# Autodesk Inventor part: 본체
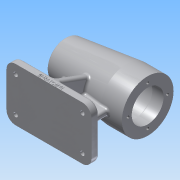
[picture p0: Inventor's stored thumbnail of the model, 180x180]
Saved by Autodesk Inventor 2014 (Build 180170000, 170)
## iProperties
Created: 2018-09
Part Number: 본체
Material: 알루미늄 6061
Document SubType Name: Modeling
Designer: 701-16
Density: 2.71 g/cm^3
Appearance: 알루미늄 - 평지
Mass: 735.408 g
Surface Area: 665.229 cm^2
Volume: 271.368 cm^3
Author: 701-16
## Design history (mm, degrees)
sketch "스케치1"
  geometry: L1 (44, 35)-(-44, 35); L2 (-56, 23)-(-56, -23); L3 (-44, -35)-(44, -35); L4 (56, -23)-(56, 23); L5 (56, 35)-(-56, -35); L6 (-56, 35)-(56, -35); A1 r 12 centre (44, -23) between (44, -35) and (56, -23); A2 r 12 centre (44, 23) between (56, 23) and (44, 35); A3 r 12 centre (-44, 23) between (-44, 35) and (-56, 23); A4 r 12 centre (-44, -23) between (-56, -23) and (-44, -35); 1 further point
  constraints: 12 end point, 8 point on circle, 8 point on line, 8 tangent, 4 centre point, 2 equal radius, 2 midpoint, 2 parallel, 1 horizontal, 1 perpendicular
  dimensions: "d0" = 112 distance of L6.end L5.end; "d1" = 70 distance of L5.end L6.start; "d2" = 12 radius of A1; "d3" = 12 radius of A2
extrude "돌출1" new body sketch "스케치1" distance "d4" = 10; taper "d5" = 0 deg
node "작업 평면1"
sketch "스케치2"
  geometry: L1 (0, 35)-(10, 35) reference; L2 (10, 35)-(10, -35) reference; L3 (10, -35)-(0, -35) reference; L4 (0, -35)-(0, 35) reference; L5 (0, 0)-(74, 0); C1 r 34 at (74, 0)
  constraints: 2 end point, 1 centre point, 1 coincident, 1 perpendicular
  dimensions: "d7" = 74 distance of L5.start L5.end; "d8" = 68 diameter of C1
extrude "돌출2" join sketch "스케치2" distance "d9" = 28; taper "d10" = 0 deg
sketch "스케치3"
  geometry: L1 (-56, 0)-(-56, 10) reference; L2 (-56, 10)-(56, 10) reference; L3 (56, 10)-(56, 0) reference; L4 (56, 0)-(-56, 0) reference; L5 (28, 108)-(56, 108) reference; L6 (56, 108)-(56, 40) reference; L7 (56, 40)-(28, 40) reference; L8 (28, 40)-(28, 108) reference; L9 (28, 74)-(-56, 74); L10 (28, 108)-(-52.315, 98.139); A1 r 80 centre (24, 74.138) between (-52.315, 98.139) and (-56, 74); 2 further points
  constraints: 4 end point, 2 point on circle, 1 centre point, 1 midpoint, 1 perpendicular
  dimensions: "d11" = 84 distance of L9.end L9.start; "d12" = 7 deg angle of L5 L10; "d14" = 80 radius of A1
revolve "회전1" sketch "스케치3" stored, may be unused: angle "d15" = 90 deg
sketch "스케치4"
  geometry: C1 r 21 at (0, 0); 1 further point
  constraints: 1 centre point
  dimensions: "d16" = 42 diameter of C1
extrude "돌출3" cut sketch "스케치4" distance "d17" = 15; taper "d18" = 0 deg
sketch "스케치5"
  geometry: C1 r 24 at (0, 0); 1 further point
  constraints: 1 centre point
  dimensions: "d19" = 48 diameter of C1
extrude "돌출4" cut sketch "스케치5" distance "d20" = 54; taper "d21" = 0 deg
sketch "스케치6"
  geometry: C1 r 21 at (0, 0); 1 further point
  constraints: 1 centre point
  dimensions: "d22" = 42 diameter of C1
extrude "돌출5" cut sketch "스케치6" distance "d23" = 12; taper "d24" = 0 deg
sketch "스케치7"
  geometry: C1 r 17.5 at (0, 0); 1 further point
  constraints: 1 centre point
  dimensions: "d25" = 35 diameter of C1
extrude "돌출6" cut sketch "스케치7" distance "d26" = 18; taper "d27" = 0 deg
sketch "스케치8"
  geometry: C1 r 16 at (0, 0); 1 further point
  constraints: 1 centre point
  dimensions: "d28" = 32 diameter of C1
extrude "돌출7" cut sketch "스케치8" distance "d29" = 4; taper "d30" = 0 deg
sketch "스케치9"
  geometry: C1 r 10.5 at (0, 0); 1 further point
  constraints: 1 centre point
  dimensions: "d31" = 21 diameter of C1
extrude "돌출8" cut sketch "스케치9" distance "d32" = 3; taper "d33" = 0 deg
hole "구멍1" diameter "d45" = 5.5; stored, may be unused: countersink angle "d49" = 90 deg, drill point angle "d51" = 0 deg; dims "d43" = 10, "d44" = 10, "d46" = 6, "d47" = 9.5, "d48" = 5.4, "d50" = 10
hole "구멍2" diameter "d54" = 5.5; stored, may be unused: countersink angle "d58" = 90 deg, drill point angle "d60" = 0 deg; dims "d52" = 10, "d53" = 10, "d55" = 6, "d56" = 9.5, "d57" = 5.4, "d59" = 10
hole "구멍3" diameter "d63" = 5.5; stored, may be unused: countersink angle "d67" = 90 deg, drill point angle "d69" = 0 deg; dims "d61" = 10, "d62" = 10, "d64" = 6, "d65" = 9.5, "d66" = 5.4, "d68" = 10
hole "구멍4" diameter "d72" = 5.5; stored, may be unused: countersink angle "d76" = 90 deg, drill point angle "d78" = 0 deg; dims "d70" = 10, "d71" = 10, "d73" = 6, "d74" = 9.5, "d75" = 5.4, "d77" = 10
sketch "스케치12" dims "d79" = 52
  geometry: 3 further points
  constraints: 1 horizontal alignment, 2 other
hole "구멍5" sketch "스케치12" at (26, 0) diameter "d80" = 3.459; stored, may be unused: countersink angle "d84" = 82 deg, drill point angle "d86" = 118 deg; dims "d81" = 8, "d82" = 3.023, "d83" = 5.4, "d85" = 11
sketch "스케치13"
  geometry: L1 (99.7, 0)-(43.7, 0); L2 (43.7, 0)-(43.7, 3); 2 further points
  constraints: 4 end point, 1 coincident, 1 horizontal, 1 perpendicular, 1 other
  dimensions: "d90" = 56 distance of L1.start L1.end; "d91" = 3 distance of L1.end L2.end
feature "엠보싱1" sketch "스케치13" dims "d0" = 112, "d1" = 70, "d2" = 12, "d3" = 12, "d92" = 0.5, "d93" = 0
fillet "모깎기1" dims "d94" = 3
fillet "모깎기6" dims "d99" = 3
sketch "스케치14"
  geometry: L1 (0, 35)-(4.577, 35) reference; L2 (4.577, 35)-(4.577, 35.5) reference; L3 (4.577, 35.5)-(4.908, 35.5) reference; L4 (4.908, 35.5)-(4.908, 35) reference; L5 (4.908, 35)-(7, 35) reference; L6 (10, 32)-(10, -32) reference; L7 (7, -35)-(0, -35) reference; L8 (0, -35)-(0, 35) reference; L9 (8.026, 34.819)-(57.039, 16.98); L10 (8.026, -34.819)-(57.039, -16.98); L11 (57.039, 16.98)-(47.649, 8.819); L12 (47.649, 8.819)-(47.649, -8.009); L13 (47.649, -8.009)-(57.039, -16.98); C1 r 30.562 at (74, 0) reference; A1 r 24 centre (74, 0) between (57.039, 16.98) and (57.039, -16.98) reference; A2 r 3 centre (7, 32) between (10, 32) and (7, 35) reference; A3 r 3 centre (7, -32) between (7, -35) and (10, -32) reference; 1 further point
  constraints: 10 end point, 5 point on circle, 2 tangent, 1 parallel
  dimensions: "d100" = 20 deg angle of L5 L9; "d101" = 20 deg angle of L7 L10
extrude "돌출11" join sketch "스케치14" stored distance "d102" = 8; taper "d103" = 0 deg
sketch "스케치15"
  geometry: L1 (-13, 50)-(41, 50) reference; L2 (41, 50)-(41, 53) reference; L3 (41, 53)-(56, 53) reference; L4 (56, 53)-(56, 49.73) reference; L5 (56, 49.73)-(45, 49.73) reference; L6 (45, 49.73)-(43.961, 48) reference; L7 (45, 46.27)-(56, 46.27) reference; L8 (56, 46.27)-(56, 40) reference; L9 (56, 40)-(28.183, 40) reference; L10 (27.818, 40.022)-(4, 42.947) reference; L11 (4, 42.947)-(4, 10) reference; L12 (4, 10)-(53, 10) reference; L13 (56, 7)-(56, 0) reference; L14 (56, 0)-(-56, 0) reference; L15 (-56, 0)-(-56, 7) reference; L16 (-53, 10)-(-4, 10) reference; L17 (-4, 10)-(-4, 43.929) reference; L18 (-4, 43.929)-(-50.372, 49.623) reference; L19 (-50.372, 98.377)-(27.818, 107.978) reference; L20 (28.183, 108)-(56, 108) reference; L21 (56, 108)-(56, 101.73) reference; L22 (56, 101.73)-(45, 101.73) reference; L23 (45, 101.73)-(43.961, 100) reference; L24 (45, 98.27)-(56, 98.27) reference; L25 (56, 98.27)-(56, 95) reference; L26 (56, 95)-(41, 95) reference; L27 (41, 95)-(41, 98) reference; L28 (41, 98)-(-13, 98) reference; L29 (-13, 98)-(-13, 95) reference; L30 (-13, 95)-(-25, 95) reference; L31 (-25, 95)-(-25, 91.5) reference; L32 (-25, 91.5)-(-43, 91.5) reference; L33 (-43, 91.5)-(-43, 90) reference; L34 (-43, 90)-(-47, 90) reference; L35 (-47, 90)-(-47, 84.5) reference; L36 (-47, 84.5)-(-50, 84.5) reference; L37 (-50, 84.5)-(-50, 63.5) reference; L38 (-50, 63.5)-(-47, 63.5) reference; L39 (-47, 63.5)-(-47, 58) reference; L40 (-47, 58)-(-43, 58) reference; L41 (-43, 58)-(-43, 56.5) reference; L42 (-43, 56.5)-(-25, 56.5) reference; L43 (-25, 56.5)-(-25, 53) reference; L44 (-25, 53)-(-13, 53) reference; L45 (-13, 53)-(-13, 50) reference; L46 (-38, 10)-(-27.007, 51.028); L47 (38, 10)-(38, 43.929); L48 (-27.282, 50)-(19.127, 46.246); L49 (19.127, 46.246)-(38, 43.929); L50 (43.961, 48)-(45, 46.27) reference; L51 (43.961, 100)-(45, 98.27) reference; A1 r 3 centre (28.183, 43) between (27.818, 40.022) and (28.183, 40) reference; A2 r 3 centre (53, 7) between (56, 7) and (53, 10) reference; A3 r 3 centre (-53, 7) between (-53, 10) and (-56, 7) reference; A4 r 3 centre (-50.007, 52.601) between (-52.89, 51.772) and (-50.372, 49.623) reference; A5 r 80 centre (24, 73.862) between (-56, 74) and (-52.89, 51.772) reference; A6 r 80 centre (24, 74.138) between (-52.89, 96.228) and (-56, 74) reference; A7 r 3 centre (-50.007, 95.399) between (-50.372, 98.377) and (-52.89, 96.228) reference; A8 r 3 centre (28.183, 105) between (28.183, 108) and (27.818, 107.978) reference; 1 further point
  constraints: 8 end point, 3 point on line, 2 parallel
  dimensions: "d104" = 18 distance from line of L15 L46.start; "d105" = 105 deg angle of L16 L46; "d106" = 18 distance from line of L13 L47.start
extrude "돌출12" join sketch "스케치15" stored distance "d107" = 8; taper "d108" = 0 deg
fillet "모깎기7" dims "d109" = 3
fillet "모깎기8" dims "d110" = 3
fillet "모깎기9" dims "d111" = 3
fillet "모깎기10" dims "d112" = 3
fillet "모깎기11" dims "d116" = 0.3
fillet "모깎기12" dims "d117" = 3
fillet "모깎기13" dims "d118" = 3
node "솔리드1"
pattern_circular "원형 패턴1" dims angle "d88" = 360 deg
node "절단 모서리 투영1"
node "절단 모서리 투영2"
node "절단 모서리 투영6"
node "절단 모서리 투영7"
other parameters: "d6" = 28
